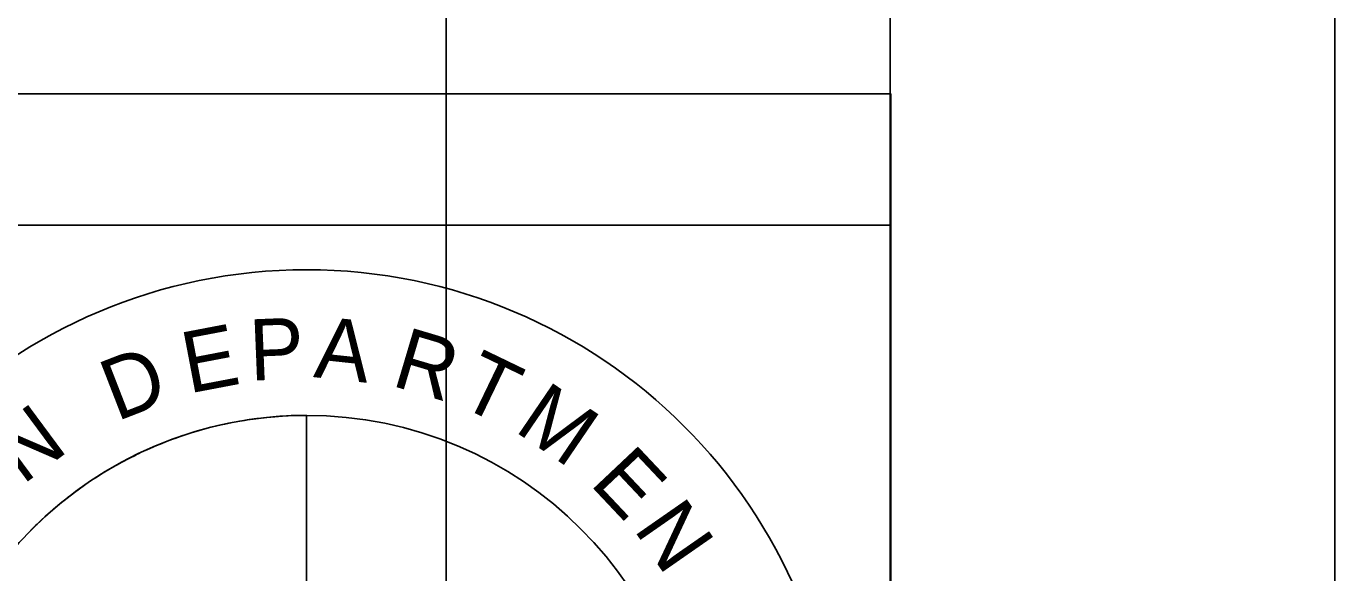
# Model space of a CAD drawing. Extents: x 0 to 1.42, y 0 to 0.92.
# Drawn here: x 1.3554 to 1.4167, y 0.2004 to 0.226 of the extents above; entities that cross this region are included whole.
import ezdxf

# ---------------------------------------------------------------- set-up
doc = ezdxf.new("R2010")
doc.units = 0
for name, color, linetype in [('#plot_layout', 7, 'Continuous'), ('#plot_shape', 7, 'Continuous'), ('P_ODOT_PLAN_Border', 7, 'Continuous'), ('P_ODOT_PLAN_General', 7, 'Continuous'), ('P_ODOT_PLAN_TBlock', 7, 'Continuous')]:
    doc.layers.add(name, color=color, linetype=linetype)

msp = doc.modelspace()

# ---------------------------------------------------------------- linework, layer by layer
at = {"layer": '#plot_layout'}
msp.add_lwpolyline([(0.083333, 0.458317), (1.375033, 0.458317), (1.375033, 0.062499), (0.083333, 0.062499)], close=True, dxfattribs=at)
at = {"layer": '#plot_shape'}
msp.add_lwpolyline([(0, 0), (1.416667, 0), (1.416667, 0.916667), (0, 0.916667)], close=True, dxfattribs=at)
at = {"layer": 'P_ODOT_PLAN_Border'}
msp.add_lwpolyline([(0.0625, 0.041667), (1.395833, 0.041667), (1.395833, 0.875), (0.0625, 0.875)], close=True, dxfattribs=at)
at = {"layer": 'P_ODOT_PLAN_General'}
msp.add_lwpolyline([(1.395867, 0.041667), (0.889038, 0.041667), (0.889038, 0.222823), (1.395867, 0.222823)], close=True, dxfattribs=at)
at = {"layer": 'P_ODOT_PLAN_TBlock'}
msp.add_lwpolyline([(0.958367, 0.041667), (1.395867, 0.041667), (1.395867, 0.216667), (0.958367, 0.216667)], close=True, dxfattribs=at)
msp.add_lwpolyline([(1.355336, 0.202122), (1.355506, 0.202297), (1.355636, 0.202429), (1.355709, 0.202502), (1.355824, 0.202614), (1.355872, 0.202661), (1.35588, 0.202668), (1.355892, 0.20268), (1.355975, 0.202759), (1.35609, 0.202867), (1.356235, 0.203001), (1.356362, 0.203117), (1.356641, 0.203361), (1.357034, 0.20369), (1.357221, 0.203841), (1.357329, 0.203926), (1.357438, 0.204009), (1.357681, 0.204192), (1.357846, 0.204314), (1.358275, 0.204614), (1.358548, 0.204797), (1.358643, 0.204858), (1.358702, 0.204896), (1.358834, 0.20498), (1.358892, 0.205016), (1.359314, 0.205271), (1.359563, 0.205414), (1.359656, 0.205466), (1.359675, 0.205477), (1.359906, 0.205603), (1.360142, 0.205727), (1.360242, 0.205779), (1.360463, 0.205889), (1.360528, 0.205921), (1.360598, 0.205955), (1.360622, 0.205967), (1.360632, 0.205972), (1.360636, 0.205973), (1.360757, 0.206031), (1.361159, 0.206214), (1.361336, 0.206291), (1.36147, 0.206348), (1.361642, 0.206419), (1.361976, 0.206551), (1.362214, 0.206641), (1.362333, 0.206684), (1.362453, 0.206727), (1.362659, 0.206798), (1.362866, 0.206867), (1.363285, 0.206998), (1.364021, 0.207202), (1.364488, 0.207314), (1.364666, 0.207353), (1.365013, 0.207425), (1.365366, 0.20749), (1.36559, 0.207528), (1.365816, 0.207563), (1.36617, 0.207612), (1.366218, 0.207618), (1.366627, 0.207665), (1.366912, 0.207693), (1.367076, 0.207706), (1.367091, 0.207707), (1.367131, 0.207711), (1.367241, 0.207718), (1.367302, 0.207723), (1.367325, 0.207724), (1.367559, 0.207738), (1.367642, 0.207742), (1.367774, 0.207748), (1.368029, 0.207756), (1.368188, 0.20776), (1.368393, 0.207762), (1.368466, 0.207762), (1.368499, 0.207762), (1.368503, 0.197904)], dxfattribs=at)
for radius in [0.025, 0.018179]:
    msp.add_circle((1.368499, 0.189583), radius, dxfattribs=at)

# ---------------------------------------------------------------- texts
for s, rotation, p in [('P', 2.30865, (1.365866, 0.209384)), ('A', 353.90454, (1.368789, 0.209556)), ('E', 10.79088, (1.362975, 0.208779)), ('R', 343.43789, (1.372412, 0.209171)), ('D', 21.21066, (1.359594, 0.207463)), ('T', 334.27595, (1.375481, 0.208298)), ('M', 325.77028, (1.378172, 0.20706)), ('N', 36.51883, (1.35519, 0.204478)), ('E', 313.3114, (1.381715, 0.204561)), ('N', 304.82916, (1.383779, 0.202448))]:
    msp.add_text(s, height=0.002869, rotation=rotation, dxfattribs=at).set_placement(p)

doc.saveas('drawing.dxf')
